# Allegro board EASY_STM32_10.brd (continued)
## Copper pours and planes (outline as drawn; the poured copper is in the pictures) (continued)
GND on BOTTOM: 0.2,76.1 2.9,76.1 3.9,77.1 3.9,79.8 47.1,79.8 47.1,77.1 48.1,76.1 50.8,76.1 50.8,3.9 48.1,3.9 47.1,2.9 47.1,0.2 3.9,0.2 3.9,2.9 2.9,3.9 0.2,3.9 ; 1 cut-out
Net_5 on BOTTOM (solid shape): 11.86,6.88 12.49,6.88 12.49,6.38 11.86,6.38 11.86,5.38 12.49,5.38 12.49,4.88 10.11,4.88 10.11,5.38 11.36,5.38 11.36,6.12 10.61,5.38 10.11,5.38 10.11,5.62 10.99,6.5 10.11,7.38 10.11,8.12 11.36,6.88 11.36,8.12 11.86,8.12

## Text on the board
Ref Des/Silkscreen Top: +3V3 | +5V | PA15 | PA14 | PC10 | PC11 | PC12 | VBAT | PC13 | NRST | VSSA | VDDA | GND | PD2 | PB3 | PB4 | PB5 | PB6 | PB7 | PB8 | PB9 | PC0 | PC1 | PC2 | PC3 | PA0 | PA1 | PA2 | PA13 | PA12 | PA11 | PA10 | PA9 | PA8 | PC9 | PC8 | PC7 | PC6 | PB15 | PB14 | PB13 | PB12 | PB11 | PB10 | PB2 | PB1 | PB0 | PC5 | PC4 | PA7 | PA6 | PA5 | PA4 | DBGU | 20112011 | BOOT0 | BOOT1 | SPEED UP YOUR INNOVATIONS | kamejoko80@yahoo.com | COPY RIGHT @ 2011 | USR_LED | PWR_LED | USB | EASY_STM32 | RESET
DIMENSION: FIGURE | SIZE | 0.4 | 0.508 | 0.8 | 0.9 | 0.914 | 1.0 | 3.0 | DRILL CHART: TOP to BOTTOM | ALL UNITS ARE IN MILLIMETERS | PLATED | NON-PLATED | QTY | 186 | 12 | 14 | 60 | 4 | 2
